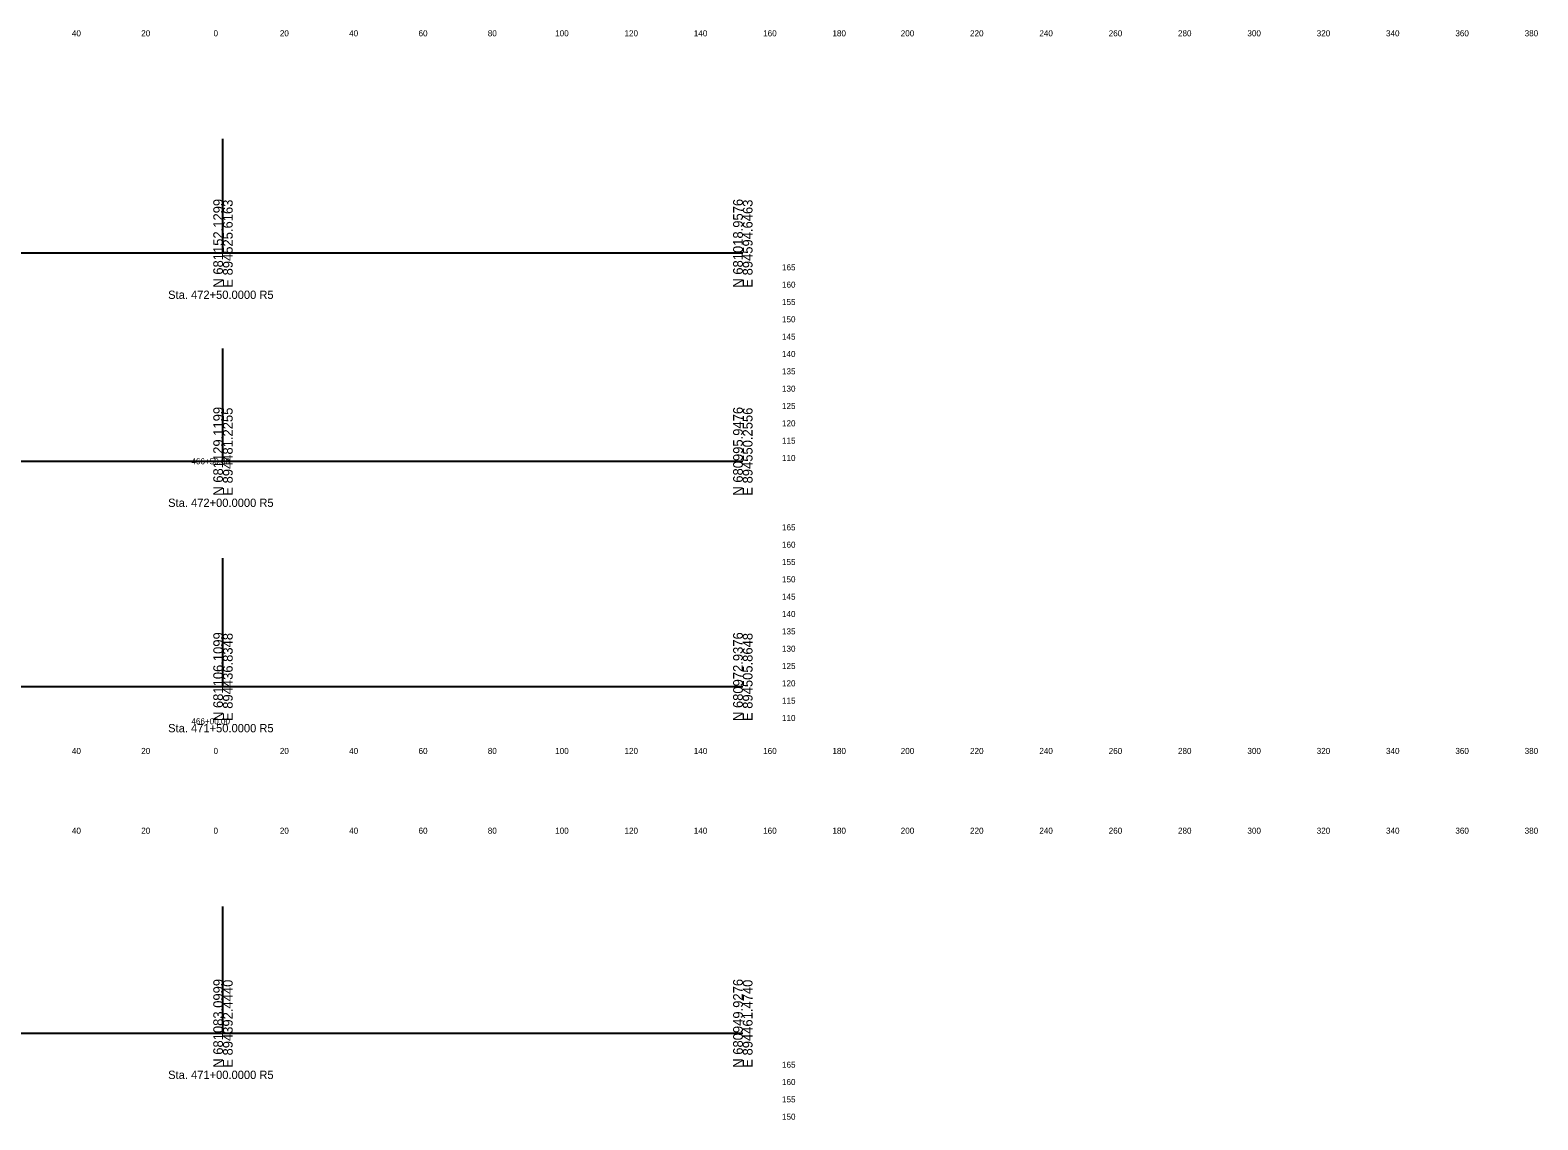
# Model space of a CAD drawing. Extents: x 21059 to 22955, y 6470 to 17494.
# Drawn here: x 21589.2 to 22024.2, y 9589.8 to 9904.1 of the extents above; entities that cross this region are included whole.
import ezdxf

# ---------------------------------------------------------------- set-up
doc = ezdxf.new("R2010")
doc.units = 0
for name, color, linetype in [('Draft_XS_Grid', 7, 'Continuous'), ('Draft_XS_Text', 7, 'Continuous'), ('DTM CONTOURS_MAJOR', 7, 'Continuous'), ('SLOPE_STAKES_FILL', 7, 'Continuous'), ('X_PROFILES_1', 7, 'Continuous')]:
    doc.layers.add(name, color=color, linetype=linetype)

msp = doc.modelspace()

# ---------------------------------------------------------------- linework, layer by layer
at = {"layer": 'DTM CONTOURS_MAJOR'}
for p, q in [((21644.84, 9839.84), (21644.84, 9872.73)), ((21494.84, 9839.84), (21644.84, 9839.84)), ((21644.84, 9839.84), (21794.84, 9839.84)), ((21644.84, 9779.84), (21644.84, 9812.28)), ((21494.84, 9779.84), (21644.84, 9779.84)), ((21644.84, 9779.84), (21794.84, 9779.84)), ((21644.84, 9714.84), (21644.84, 9751.82)), ((21494.84, 9714.84), (21644.84, 9714.84)), ((21644.84, 9714.84), (21794.84, 9714.84)), ((21644.84, 9614.84), (21644.84, 9651.37)), ((21494.84, 9614.84), (21644.84, 9614.84)), ((21644.84, 9614.84), (21794.84, 9614.84))]:
    msp.add_line(p, q, dxfattribs=at)

# ---------------------------------------------------------------- texts
at = {"layer": 'Draft_XS_Grid'}
for s, p in [('  165  ', (21804.84, 9834.84)), ('  160  ', (21804.84, 9829.84)), ('  155  ', (21804.84, 9824.84)), ('  150  ', (21804.84, 9819.84)), ('  145  ', (21804.84, 9814.84)), ('  140  ', (21804.84, 9809.84)), ('  135  ', (21804.84, 9804.84)), ('  130  ', (21804.84, 9799.84)), ('  125  ', (21804.84, 9794.84)), ('  120  ', (21804.84, 9789.84)), ('  115  ', (21804.84, 9784.84)), ('  110  ', (21804.84, 9779.84)), ('  165  ', (21804.84, 9759.84)), ('  160  ', (21804.84, 9754.84)), ('  155  ', (21804.84, 9749.84)), ('  150  ', (21804.84, 9744.84)), ('  145  ', (21804.84, 9739.84)), ('  140  ', (21804.84, 9734.84)), ('  135  ', (21804.84, 9729.84)), ('  130  ', (21804.84, 9724.84)), ('  125  ', (21804.84, 9719.84)), ('  120  ', (21804.84, 9714.84)), ('  115  ', (21804.84, 9709.84)), ('  110  ', (21804.84, 9704.84)), ('  165  ', (21804.84, 9604.84)), ('  160  ', (21804.84, 9599.84)), ('  155  ', (21804.84, 9594.84)), ('  150  ', (21804.84, 9589.84))]:
    msp.add_text(s, height=1.75, dxfattribs=at).set_placement(p)
at = {"layer": 'Draft_XS_Text'}
for s, p in [('  40  ', (21599.95, 9902.34)), ('  20  ', (21619.95, 9902.34)), ('  0  ', (21640.81, 9902.34)), ('  0  ', (21640.81, 9902.34)), ('  20  ', (21659.95, 9902.34)), ('  40  ', (21679.95, 9902.34)), ('  60  ', (21699.97, 9902.34)), ('  80  ', (21719.95, 9902.34)), ('  100  ', (21739.39, 9902.34)), ('  120  ', (21759.39, 9902.34)), ('  140  ', (21779.39, 9902.34)), ('  160  ', (21799.4, 9902.34)), ('  180  ', (21819.39, 9902.34)), ('  200  ', (21839.1, 9902.34)), ('  220  ', (21859.1, 9902.34)), ('  240  ', (21879.1, 9902.34)), ('  260  ', (21899.11, 9902.34)), ('  280  ', (21919.1, 9902.34)), ('  300  ', (21939.13, 9902.34)), ('  320  ', (21959.13, 9902.34)), ('  340  ', (21979.13, 9902.34)), ('  360  ', (21999.14, 9902.34)), ('  380  ', (22019.13, 9902.34)), ('  40  ', (21599.95, 9695.34)), ('  20  ', (21619.95, 9695.34)), ('  0  ', (21640.81, 9695.34)), ('  0  ', (21640.81, 9695.34)), ('  20  ', (21659.95, 9695.34)), ('  40  ', (21679.95, 9695.34)), ('  60  ', (21699.97, 9695.34)), ('  80  ', (21719.95, 9695.34)), ('  100  ', (21739.39, 9695.34)), ('  120  ', (21759.39, 9695.34)), ('  140  ', (21779.39, 9695.34)), ('  160  ', (21799.4, 9695.34)), ('  180  ', (21819.39, 9695.34)), ('  200  ', (21839.1, 9695.34)), ('  220  ', (21859.1, 9695.34)), ('  240  ', (21879.1, 9695.34)), ('  260  ', (21899.11, 9695.34)), ('  280  ', (21919.1, 9695.34)), ('  300  ', (21939.13, 9695.34)), ('  320  ', (21959.13, 9695.34)), ('  340  ', (21979.13, 9695.34)), ('  360  ', (21999.14, 9695.34)), ('  380  ', (22019.13, 9695.34)), ('  40  ', (21599.95, 9672.34)), ('  20  ', (21619.95, 9672.34)), ('  0  ', (21640.81, 9672.34)), ('  0  ', (21640.81, 9672.34)), ('  20  ', (21659.95, 9672.34)), ('  40  ', (21679.95, 9672.34)), ('  60  ', (21699.97, 9672.34)), ('  80  ', (21719.95, 9672.34)), ('  100  ', (21739.39, 9672.34)), ('  120  ', (21759.39, 9672.34)), ('  140  ', (21779.39, 9672.34)), ('  160  ', (21799.4, 9672.34)), ('  180  ', (21819.39, 9672.34)), ('  200  ', (21839.1, 9672.34)), ('  220  ', (21859.1, 9672.34)), ('  240  ', (21879.1, 9672.34)), ('  260  ', (21899.11, 9672.34)), ('  280  ', (21919.1, 9672.34)), ('  300  ', (21939.13, 9672.34)), ('  320  ', (21959.13, 9672.34)), ('  340  ', (21979.13, 9672.34)), ('  360  ', (21999.14, 9672.34)), ('  380  ', (22019.13, 9672.34))]:
    msp.add_text(s, height=1.75, dxfattribs=at).set_placement(p)
at = {"layer": 'DTM CONTOURS_MAJOR'}
for s, p in [('N 681152.1299', (21644.84, 9829.84)), ('E 894525.6163', (21647.64, 9829.84)), ('N 681018.9576', (21794.84, 9829.84)), ('E 894594.6463', (21797.64, 9829.84)), ('N 681129.1199', (21644.84, 9769.84)), ('E 894481.2255', (21647.64, 9769.84)), ('N 680995.9476', (21794.84, 9769.84)), ('E 894550.2556', (21797.64, 9769.84)), ('N 681106.1099', (21644.84, 9704.84)), ('E 894436.8348', (21647.64, 9704.84)), ('N 680972.9376', (21794.84, 9704.84)), ('E 894505.8648', (21797.64, 9704.84)), ('N 681083.0999', (21644.84, 9604.84)), ('E 894392.4440', (21647.64, 9604.84)), ('N 680949.9276', (21794.84, 9604.84)), ('E 894461.4740', (21797.64, 9604.84))]:
    msp.add_text(s, height=2.8, rotation=90, dxfattribs=at).set_placement(p)
at = {"layer": 'SLOPE_STAKES_FILL'}
for s, p in [('  466+50.00  ', (21634.43, 9778.89)), ('  466+00.00  ', (21634.43, 9703.89))]:
    msp.add_text(s, height=1.75, dxfattribs=at).set_placement(p)
at = {"layer": 'X_PROFILES_1'}
for s, p in [('Sta. 472+50.0000 R5', (21629.02, 9826.59)), ('Sta. 472+00.0000 R5', (21629.02, 9766.59)), ('Sta. 471+50.0000 R5', (21629.02, 9701.59)), ('Sta. 471+00.0000 R5', (21629.02, 9601.59))]:
    msp.add_text(s, height=2.4, dxfattribs=at).set_placement(p)

doc.saveas('drawing.dxf')
